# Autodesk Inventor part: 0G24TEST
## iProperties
Created: 2007-01
Part Number: 0G24TEST
Document SubType Name: Blech
Designer: R.Pilz
Description: Blech lt. Tab.
GesGewicht: 0,6kg
ArtNrPrefix: HZ
ArtNrAuto: 0
EDVNum=ArtNr: 0
Bez=Mat: 0
ArtNrBackSpace: 0
EDVNrBackSpace: 0
EDVNrAuto: 0
ProdGruppe: ÜKWW
ProdBezeichnung: Blende
ArtNr: lt. Tab.
EDVNr: lt. Tab
KommaZuschnitt: 0
Zeichnungsnummer: 0G24 TE ST
Konstrukteur: R.Pilz
Erstellungsdatum: 10.01.2007
Material: Standard
Author: R.Pilz
Title: Platte
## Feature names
1. Grobblech1
